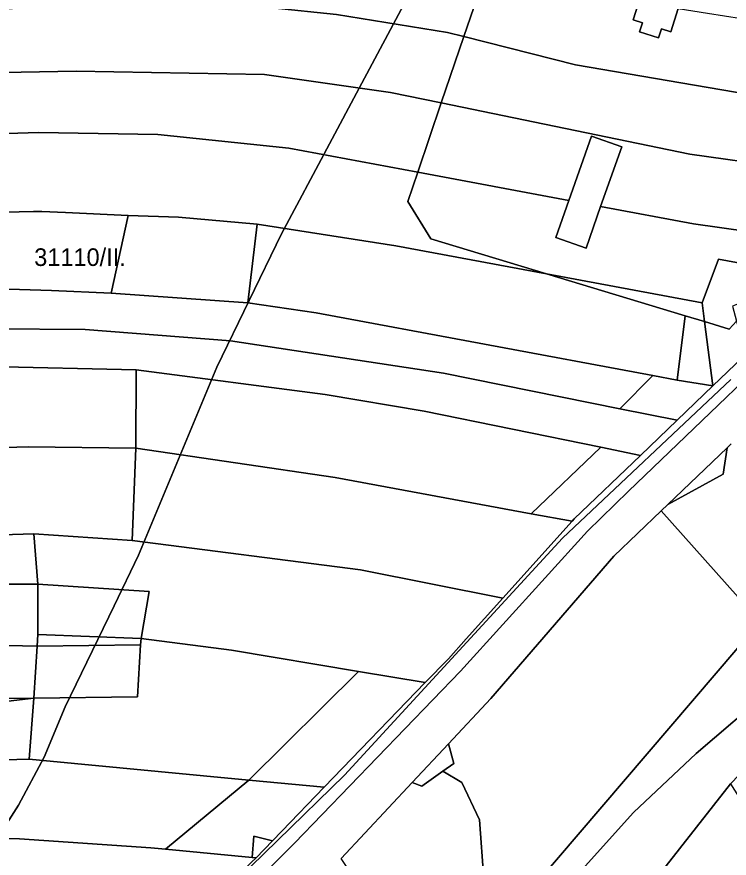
# Model space of a CAD drawing. Extents: x -535894 to -532834, y -1165802 to -1163645.
# Drawn here: x -534145.6 to -533943.2, y -1165184 to -1164945 of the extents above; entities that cross this region are included whole.
import ezdxf

# ---------------------------------------------------------------- set-up
doc = ezdxf.new("R2010")
doc.units = 0
for name, color, linetype in [('95560013', 7, 'Continuous'), ('95590013', 7, 'Continuous'), ('95610013', 7, 'Continuous'), ('95630013', 7, 'Continuous'), ('95640013', 7, 'Continuous'), ('95660013', 7, 'Continuous')]:
    doc.layers.add(name, color=color, linetype=linetype)

msp = doc.modelspace()

# ---------------------------------------------------------------- linework, layer by layer
at = {"layer": '95560013'}
for points in [[(-534078.29, -1164923.33), (-534077.35, -1164923.36), (-534012.88, -1164933.73), (-534018.61, -1164950.58), (-534023.28, -1164949.4), (-534054.83, -1164944.3), (-534091.39, -1164940.53), (-534086.44, -1164936.35), (-534082.19, -1164930.46)], [(-534102.62, -1164940.95), (-534091.39, -1164940.53), (-534054.83, -1164944.3), (-534023.28, -1164949.4), (-534018.61, -1164950.58), (-534025.02, -1164969.45), (-534039.47, -1164966.47), (-534075.29, -1164961.33), (-534128.74, -1164960.43), (-534175.69, -1164961.26), (-534214.43, -1164963.28), (-534302.49, -1164968.05), (-534305.74, -1164957.13), (-534302.89, -1164950.93), (-534250.92, -1164946.98), (-534197.15, -1164944.46), (-534154.72, -1164942.88), (-534128.76, -1164941.92)], [(-534175.69, -1164961.26), (-534128.74, -1164960.43), (-534075.29, -1164961.33), (-534039.47, -1164966.47), (-534025.02, -1164969.45), (-534031.7, -1164989.14), (-534068.38, -1164982.26), (-534105.6, -1164978.41), (-534139.49, -1164977.82), (-534213.51, -1164980.26), (-534214.43, -1164963.28)], [(-534139.49, -1164977.82), (-534105.6, -1164978.41), (-534068.38, -1164982.26), (-534031.7, -1164989.14), (-534034.52, -1164997.43), (-534028.02, -1165008.03), (-533995.12, -1165018), (-534037.89, -1165010.01), (-534077.31, -1165003.9), (-534099.72, -1165001.87), (-534114.02, -1165001.45), (-534131.78, -1165000.56), (-534138.54, -1165000.28), (-534140.89, -1165000.32), (-534153.33, -1165000.55), (-534177.53, -1165001), (-534200.18, -1165002.04), (-534218.76, -1165002.89), (-534219.6, -1164983.53), (-534219.73, -1164980.58), (-534213.51, -1164980.26)], [(-534140.89, -1165000.32), (-534138.54, -1165000.28), (-534131.78, -1165000.56), (-534114.02, -1165001.45), (-534118.77, -1165023.54), (-534135.8, -1165022.76), (-534144.89, -1165022.48), (-534152.58, -1165022.25), (-534152.95, -1165011.58), (-534153.33, -1165000.55)], [(-534114.02, -1165001.45), (-534099.72, -1165001.87), (-534077.31, -1165003.9), (-534080, -1165026.25), (-534118.77, -1165023.54)], [(-534077.31, -1165003.9), (-534037.89, -1165010.01), (-533995.12, -1165018), (-533955.72, -1165029.92), (-533958, -1165048.21), (-533964.89, -1165046.93), (-534060.6, -1165029.11), (-534080, -1165026.25)], [(-534152.58, -1165022.25), (-534144.89, -1165022.48), (-534135.8, -1165022.76), (-534118.77, -1165023.54), (-534080, -1165026.25), (-534060.6, -1165029.11), (-533964.89, -1165046.93), (-533974.3, -1165056.33), (-534024.39, -1165046.24), (-534084.94, -1165037.08), (-534126.21, -1165033.79), (-534152.16, -1165033.67), (-534152.25, -1165030.59)], [(-534152.16, -1165033.67), (-534126.21, -1165033.79), (-534084.94, -1165037.08), (-534024.39, -1165046.24), (-533974.3, -1165056.33), (-533958.04, -1165059.61), (-533968.43, -1165069.59), (-533979.67, -1165067.29), (-534029.93, -1165057.03), (-534057.97, -1165052.34), (-534111.7, -1165045.25), (-534153.61, -1165044.37)], [(-534111.7, -1165045.25), (-534057.97, -1165052.34), (-534029.93, -1165057.03), (-533979.67, -1165067.29), (-533999.48, -1165086.16), (-534055.2, -1165075.84), (-534111.79, -1165067.58)], [(-533958, -1165048.21), (-533947.86, -1165049.82), (-533958.04, -1165059.61), (-533974.3, -1165056.33), (-533964.89, -1165046.93)], [(-534111.79, -1165067.58), (-534112.8, -1165093.8), (-534140.8, -1165091.86), (-534180.28, -1165093.1), (-534189.17, -1165093.38), (-534216.42, -1165094.93), (-534226.11, -1165068.82), (-534213.51, -1165068.88), (-534190.1, -1165068.58), (-534142.42, -1165067.13)], [(-534111.79, -1165067.58), (-534055.2, -1165075.84), (-533999.48, -1165086.16), (-533987.84, -1165088.32), (-534007.52, -1165110.17), (-534047.99, -1165102.16), (-534112.8, -1165093.8)], [(-533979.67, -1165067.29), (-533968.43, -1165069.59), (-533987.24, -1165087.66), (-533987.84, -1165088.32), (-533999.48, -1165086.16)], [(-534140.8, -1165091.86), (-534112.8, -1165093.8), (-534047.99, -1165102.16), (-534007.52, -1165110.17), (-534017.92, -1165121.72), (-534023, -1165127.36), (-534029.56, -1165134.15), (-534048.54, -1165130.97), (-534084.59, -1165124.94), (-534110.26, -1165121.6), (-534108.01, -1165108.24), (-534139.68, -1165106.21)], [(-534108.01, -1165108.24), (-534110.26, -1165121.6), (-534139.68, -1165120.52), (-534139.68, -1165106.21)], [(-534139.68, -1165120.52), (-534110.26, -1165121.6), (-534110.44, -1165123.41), (-534139.87, -1165123.82)], [(-534160.98, -1165123.32), (-534139.87, -1165123.82), (-534140.75, -1165138.6), (-534170.15, -1165138.97), (-534169.88, -1165123.1)], [(-534110.44, -1165123.41), (-534110.26, -1165121.6), (-534084.59, -1165124.94), (-534048.54, -1165130.97), (-534079.72, -1165161.87), (-534142.14, -1165155.94), (-534140.75, -1165138.6), (-534111.31, -1165138.24)], [(-534139.87, -1165123.82), (-534110.44, -1165123.41), (-534111.31, -1165138.24), (-534140.75, -1165138.6)], [(-534048.54, -1165130.97), (-534029.56, -1165134.15), (-534058.31, -1165163.91), (-534079.72, -1165161.87)], [(-534170.15, -1165138.97), (-534140.75, -1165138.6), (-534148.07, -1165139.43), (-534189.99, -1165140.23), (-534199.83, -1165141.58), (-534200.14, -1165139.35), (-534192.83, -1165139.25), (-534192.75, -1165139.53), (-534191.54, -1165139.24), (-534190.2, -1165139.22)], [(-534140.75, -1165138.6), (-534142.14, -1165155.94), (-534197.6, -1165157.43), (-534199.83, -1165141.58), (-534189.99, -1165140.23), (-534148.07, -1165139.43)], [(-534197.6, -1165157.43), (-534142.14, -1165155.94), (-534079.72, -1165161.87), (-534103.37, -1165181.48), (-534107.5, -1165181.08), (-534144.9, -1165178.54), (-534196.09, -1165177.34)], [(-534079.72, -1165161.87), (-534058.31, -1165163.91), (-534070.32, -1165176.35), (-534073, -1165179.11), (-534078.28, -1165177.81), (-534078.8, -1165183.83), (-534103.37, -1165181.48)], [(-534196.09, -1165177.34), (-534144.9, -1165178.54), (-534107.5, -1165181.08), (-534103.37, -1165181.48), (-534078.8, -1165183.83), (-534077.66, -1165183.91), (-534078.91, -1165185.19), (-534097.29, -1165204.09), (-534111.65, -1165203.25), (-534176.94, -1165199.42), (-534196.74, -1165197.75)], [(-534078.28, -1165177.81), (-534073, -1165179.11), (-534077.66, -1165183.91), (-534078.8, -1165183.83)]]:
    msp.add_lwpolyline(points, close=True, dxfattribs=at)
at = {"layer": '95590013'}
for points in [[(-534111.7, -1165045.25), (-534111.79, -1165067.58), (-534142.42, -1165067.13), (-534190.1, -1165068.58), (-534213.51, -1165068.88), (-534215.59, -1165063.71), (-534190.8, -1165063.47), (-534193.26, -1165045.43), (-534153.61, -1165044.37)], [(-534180.28, -1165093.1), (-534140.8, -1165091.86), (-534139.68, -1165106.21), (-534159.84, -1165106.18), (-534179.27, -1165106.14)], [(-534139.68, -1165106.21), (-534139.68, -1165120.52), (-534139.87, -1165123.82), (-534160.98, -1165123.32), (-534160.14, -1165110.71), (-534159.84, -1165106.18)]]:
    msp.add_lwpolyline(points, close=True, dxfattribs=at)
at = {"layer": '95610013'}
msp.add_lwpolyline([(-533934.45, -1165116.87), (-533962.53, -1165085.32), (-533960.64, -1165083.51), (-533944.91, -1165074.95), (-533943.82, -1165067.47), (-533942.64, -1165066.34)], dxfattribs=at)
for points in [[(-533944.91, -1165074.95), (-533960.64, -1165083.51), (-533943.82, -1165067.47)], [(-533962.53, -1165085.32), (-533934.45, -1165116.87), (-533940.8, -1165124.3), (-534005.15, -1165199.61), (-534012.92, -1165190.05), (-534014.17, -1165173.12), (-534019.14, -1165162.52), (-534024.54, -1165159.35), (-534021.42, -1165157.14), (-534022.96, -1165151.54), (-534010.91, -1165138.64), (-533976.02, -1165098.2)], [(-533940.8, -1165124.3), (-533927.13, -1165137.47), (-533922.67, -1165144.99), (-533928.42, -1165147.92), (-533942.82, -1165162.9), (-533962.19, -1165187.57), (-533989.71, -1165212.03), (-534005.15, -1165199.61)], [(-534021.42, -1165157.14), (-534024.54, -1165159.35), (-534030.52, -1165163.57), (-534033.26, -1165162.58), (-534022.96, -1165151.54)], [(-534024.54, -1165159.35), (-534019.14, -1165162.52), (-534014.17, -1165173.12), (-534012.92, -1165190.05), (-534005.15, -1165199.61), (-533989.71, -1165212.03), (-533992.77, -1165214.76), (-533945.33, -1165285.03), (-533972.2, -1165304.55), (-534018.44, -1165236.03), (-534020.37, -1165233.16), (-534053.42, -1165184.18), (-534033.26, -1165162.58), (-534030.52, -1165163.57)], [(-533962.19, -1165187.57), (-533942.82, -1165162.9), (-533914.6, -1165207.64), (-533885.93, -1165251.42), (-533945.33, -1165285.03), (-533992.77, -1165214.76), (-533989.71, -1165212.03)]]:
    msp.add_lwpolyline(points, close=True, dxfattribs=at)
at = {"layer": '95630013'}
for points in [[(-534136.8, -1165249.37), (-534066.72, -1165179.82), (-534019.59, -1165130.92), (-533983.52, -1165091.15), (-533971.79, -1165079.79), (-533913.79, -1165024.04)], [(-533942.64, -1165066.34), (-533943.82, -1165067.47), (-533960.64, -1165083.51), (-533962.53, -1165085.32), (-533976.02, -1165098.2), (-534010.91, -1165138.64), (-534022.96, -1165151.54), (-534033.26, -1165162.58), (-534053.42, -1165184.18)]]:
    msp.add_lwpolyline(points, dxfattribs=at)
at = {"layer": '95640013'}
for points in [[(-533937.82, -1164879.8), (-533947.31, -1164909.72), (-533942.09, -1164911.38), (-533944.88, -1164920.18), (-533950.1, -1164918.52), (-533951.96, -1164924.41), (-533957.74, -1164942.58), (-533959.85, -1164949.22), (-533962.47, -1164948.39), (-533963.29, -1164950.96), (-533968.66, -1164949.26), (-533967.85, -1164946.68), (-533970.51, -1164945.79), (-533968.93, -1164940.8), (-533963.09, -1164922.39), (-533948.5, -1164876.42)], [(-534012.88, -1164933.73), (-534002.31, -1164935.43), (-534002.59, -1164936.19), (-533995.11, -1164939.02), (-533994.24, -1164936.72), (-533968.93, -1164940.8), (-533970.51, -1164945.79), (-533967.85, -1164946.68), (-533968.66, -1164949.26), (-533963.29, -1164950.96), (-533962.47, -1164948.39), (-533959.85, -1164949.22), (-533957.74, -1164942.58), (-533949.39, -1164943.93), (-533872.1, -1164956.08), (-533887.6, -1164973.66), (-533934.25, -1164967.65), (-533986.88, -1164958.63), (-534018.61, -1164950.58)], [(-534018.61, -1164950.58), (-533986.88, -1164958.63), (-533934.25, -1164967.65), (-533887.6, -1164973.66), (-533903.09, -1164991.22), (-533954.36, -1164984.01), (-534025.02, -1164969.45)], [(-533982.32, -1164978.93), (-533988.74, -1164997.2), (-534031.7, -1164989.14), (-534025.02, -1164969.45), (-533954.36, -1164984.01), (-533903.09, -1164991.22), (-533909.61, -1164998.62), (-533914.87, -1165004.11), (-533921.79, -1165008.29), (-533953.32, -1165003.84), (-533979.75, -1164998.88), (-533973.77, -1164981.91)], [(-533982.32, -1164978.93), (-533973.77, -1164981.91), (-533979.75, -1164998.88), (-533983.9, -1165010.68), (-533992.43, -1165007.68), (-533988.74, -1164997.2)], [(-534031.7, -1164989.14), (-533988.74, -1164997.2), (-533992.43, -1165007.68), (-533983.9, -1165010.68), (-533979.75, -1164998.88), (-533953.32, -1165003.84), (-533921.79, -1165008.29), (-533934.5, -1165015.99), (-533946.24, -1165013.85), (-533950.91, -1165026.24), (-533995.12, -1165018), (-534028.02, -1165008.03), (-534034.52, -1164997.43)], [(-533921.79, -1165008.29), (-533914.87, -1165004.11), (-533933.76, -1165023.78), (-533942.33, -1165027.2), (-533941.12, -1165031.45), (-533943.27, -1165033.69), (-533950.22, -1165031.59), (-533950.91, -1165026.24), (-533946.24, -1165013.85), (-533934.5, -1165015.99)], [(-533995.12, -1165018), (-533950.91, -1165026.24), (-533950.22, -1165031.59), (-533955.72, -1165029.92)], [(-533955.72, -1165029.92), (-533950.22, -1165031.59), (-533947.86, -1165049.82), (-533958, -1165048.21)], [(-533943.27, -1165033.69), (-533941.12, -1165031.45), (-533939.32, -1165037.78), (-533939.43, -1165041.74), (-533947.86, -1165049.82), (-533950.22, -1165031.59)]]:
    msp.add_lwpolyline(points, close=True, dxfattribs=at)
for points in [[(-533913.79, -1165024.04), (-533971.79, -1165079.79), (-533983.52, -1165091.15), (-534019.59, -1165130.92), (-534066.72, -1165179.82), (-534136.8, -1165249.37)], [(-534078.91, -1165185.19), (-534077.66, -1165183.91), (-534073, -1165179.11), (-534070.32, -1165176.35), (-534058.31, -1165163.91), (-534029.56, -1165134.15), (-534023, -1165127.36), (-534017.92, -1165121.72), (-534007.52, -1165110.17), (-533987.84, -1165088.32), (-533987.24, -1165087.66), (-533968.43, -1165069.59), (-533958.04, -1165059.61), (-533947.86, -1165049.82), (-533939.43, -1165041.74)]]:
    msp.add_lwpolyline(points, dxfattribs=at)
at = {"layer": '95660013'}
for points in [[(-534023.02, -1164917.81), (-534049.1, -1164966.67), (-534062.187, -1164991.188), (-534065.342, -1164997.098), (-534070.44, -1165006.65), (-534088.76, -1165044.56), (-534111.06, -1165097.92), (-534117.996, -1165112.316), (-534131.852, -1165141.076), (-534137.82, -1165155.34), (-534145.14, -1165168.96), (-534153.03, -1165181.22), (-534158.213, -1165186.838)], [(-534158.213, -1165186.838), (-534153.03, -1165181.22), (-534145.14, -1165168.96), (-534137.82, -1165155.34), (-534131.852, -1165141.076), (-534117.996, -1165112.316), (-534111.06, -1165097.92), (-534088.76, -1165044.56), (-534070.44, -1165006.65), (-534065.342, -1164997.098), (-534062.187, -1164991.188), (-534049.1, -1164966.67), (-534023.02, -1164917.81)], [(-534504, -1165364.91), (-534479.15, -1165348.82), (-534459.071, -1165335.819), (-534440.92, -1165327.96), (-534400.789, -1165317.92), (-534366.86, -1165313.619), (-534340.91, -1165310.331), (-534288.01, -1165303.627), (-534259.201, -1165299.977), (-534247.08, -1165300.4), (-534235.298, -1165303.278), (-534220.661, -1165306.853), (-534211.72, -1165306.77), (-534205.67, -1165305.18), (-534198.42, -1165301.519), (-534191.96, -1165296.599), (-534183.05, -1165287.34), (-534159.56, -1165262.93), (-534128.66, -1165234.701), (-534052.52, -1165160.48), (-533990.56, -1165093.1), (-533942.78, -1165048.02)], [(-533942.78, -1165048.02), (-533990.56, -1165093.1), (-534052.52, -1165160.48), (-534128.66, -1165234.701)], [(-533985.872, -1165188.218), (-533970.41, -1165171.07), (-533952.57, -1165154.34), (-533931.15, -1165135.95)], [(-533931.15, -1165135.95), (-533952.57, -1165154.34), (-533970.41, -1165171.07), (-533985.872, -1165188.218)]]:
    msp.add_lwpolyline(points, dxfattribs=at)

# ---------------------------------------------------------------- texts
msp.add_text('31110/II.', height=5, rotation=0, dxfattribs=at).set_placement((-534140.68, -1165015.769))

doc.saveas('drawing.dxf')
